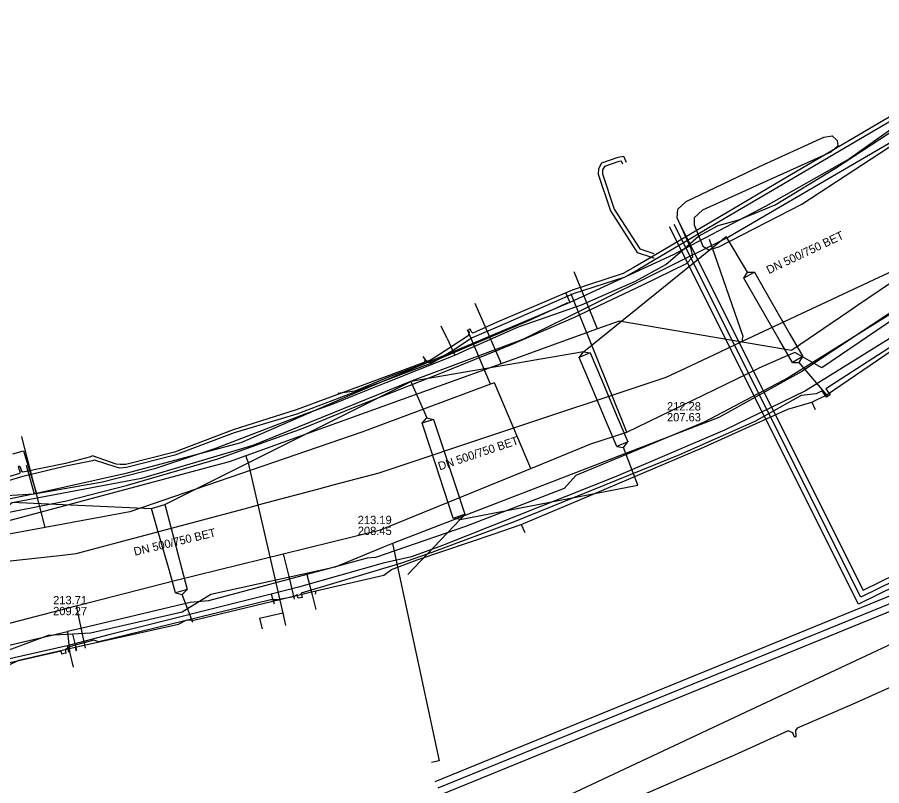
# Model space of a CAD drawing. Extents: x -600309 to -598967, y -1161267 to -1160292.
# Drawn here: x -599618 to -599534.7, y -1161216.6 to -1161142.6 of the extents above; entities that cross this region are included whole.
import ezdxf

# ---------------------------------------------------------------- set-up
doc = ezdxf.new("R2010")
doc.units = 0
for name, color, linetype in [('Vrstva 12', 7, 'Continuous'), ('Vrstva 13', 7, 'Continuous'), ('Vrstva 16', 7, 'Continuous'), ('Vrstva 37', 7, 'Continuous'), ('Vrstva 38', 7, 'Continuous'), ('Vrstva 42', 7, 'Continuous'), ('Vrstva 54', 7, 'Continuous'), ('Vrstva 55', 7, 'Continuous'), ('Vrstva 58', 7, 'Continuous'), ('Vrstva 9', 7, 'Continuous')]:
    doc.layers.add(name, color=color, linetype=linetype)

msp = doc.modelspace()

# ---------------------------------------------------------------- linework, layer by layer
at = {"layer": 'Vrstva 12'}
for p, q in [((-599576.56, -1161173.52), (-599577.125, -1161172.329)), ((-599576.56, -1161173.52), (-599577.125, -1161172.329)), ((-599589.565, -1161198.221), (-599589.204, -1161199.616)), ((-599589.56, -1161198.23), (-599589.204, -1161199.616))]:
    msp.add_line(p, q, dxfattribs=at)
for points in [[(-599521.7, -1161144.87), (-599526.65, -1161148.29), (-599537.79, -1161156.19), (-599545.87, -1161160.77), (-599553.69, -1161164.87)], [(-599560.46, -1161168.89), (-599558.43, -1161168), (-599555.5, -1161166.4), (-599553.67, -1161164.8), (-599552.34, -1161163.64), (-599550.44, -1161162.63), (-599548.47, -1161162.08), (-599544.96, -1161160.64), (-599539.13, -1161157.11), (-599529.68, -1161150.91)], [(-599513.31, -1161157.36), (-599514.8, -1161158.38), (-599542.4, -1161176.7), (-599550.4, -1161181.13), (-599580.66, -1161192.82)], [(-599553.69, -1161164.87), (-599554.78, -1161165.44)], [(-599554.78, -1161165.44), (-599564.73, -1161170.04)], [(-599574.64, -1161174.59), (-599569.69, -1161172.4), (-599563.61, -1161170.27), (-599560.46, -1161168.89)], [(-599565.12, -1161169.15), (-599564.73, -1161170.04)], [(-599564.73, -1161170.04), (-599586.21, -1161179.11), (-599596.44, -1161183.57)], [(-599533.66, -1161171.05), (-599543.7, -1161177.29), (-599551.8, -1161181.57), (-599564.18, -1161186.71), (-599565.3, -1161187.97), (-599574.8, -1161191.62), (-599583.47, -1161194.61), (-599584.26, -1161194.68), (-599587.79, -1161195.63)], [(-599576.56, -1161173.52), (-599575.81, -1161175.11)], [(-599575.81, -1161175.11), (-599574.64, -1161174.59)], [(-599616.34, -1161188.47), (-599609.76, -1161187.32), (-599604.63, -1161186), (-599598.84, -1161184.09), (-599590.23, -1161180.76), (-599587.56, -1161179.8), (-599585.34, -1161178.92), (-599582.44, -1161177.75), (-599575.81, -1161175.11)], [(-599596.44, -1161183.57), (-599607.65, -1161186.57), (-599616.14, -1161188.46)], [(-599618.42, -1161184.62), (-599617.37, -1161184.34), (-599616.14, -1161188.46)], [(-599617.13, -1161185.71), (-599616.34, -1161188.47)], [(-599616.14, -1161188.46), (-599627.44, -1161190.76), (-599644.99, -1161193.72), (-599655.61, -1161195.18), (-599659.69, -1161195.76)], [(-599642.07, -1161193.68), (-599639.42, -1161193.16), (-599622.53, -1161189.29), (-599620.66, -1161188.74), (-599616.34, -1161188.47)], [(-599581.84, -1161193.27), (-599582.62, -1161193.58), (-599587.34, -1161195.54)], [(-599580.66, -1161192.82), (-599581.84, -1161193.27)], [(-599581.84, -1161193.27), (-599577.34, -1161214.2), (-599578.08, -1161214.36)], [(-599587.34, -1161195.54), (-599599.33, -1161198.18), (-599602.08, -1161199.87), (-599610.93, -1161201.9)], [(-599587.79, -1161195.63), (-599590.08, -1161196.25)], [(-599590.08, -1161196.25), (-599599.56, -1161198.8), (-599601.31, -1161198.95), (-599611.18, -1161201.3)], [(-599590.08, -1161196.25), (-599589.56, -1161198.23)], [(-599611.18, -1161201.3), (-599613.15, -1161201.76)], [(-599628.27, -1161205.28), (-599613.15, -1161201.76)], [(-599615.01, -1161202.14), (-599616.64, -1161202.75)], [(-599612.66, -1161202), (-599615.01, -1161202.14)], [(-599613.15, -1161201.76), (-599612.95, -1161203.7)], [(-599610.93, -1161201.9), (-599612.66, -1161202)], [(-599612.66, -1161202), (-599612.28, -1161203.54)], [(-599616.64, -1161202.75), (-599619.06, -1161203.65)], [(-599612.948, -1161203.716), (-599612.602, -1161205.176)], [(-599612.948, -1161203.716), (-599612.602, -1161205.176)]]:
    msp.add_lwpolyline(points, dxfattribs=at)
at = {"layer": 'Vrstva 13'}
for points in [[(-599411.725, -1161101.732), (-599414.519, -1161102.315), (-599450.573, -1161109.837), (-599460.653, -1161116.976), (-599462.737, -1161118.461), (-599483.111, -1161132.905), (-599490.491, -1161138.137), (-599508.933, -1161151.212), (-599509.583, -1161151.672), (-599510.091, -1161152.018), (-599523.741, -1161161.304), (-599533.935, -1161168.24), (-599537.024, -1161170.341), (-599537.86, -1161170.91)], [(-599548.15, -1161173.861), (-599548.1, -1161173.57), (-599548.057, -1161173.319), (-599551.27, -1161163.96)], [(-599562.071, -1161172.593), (-599562.17, -1161172.353), (-599564.326, -1161167.076)], [(-599571.356, -1161175.949), (-599571.43, -1161175.741), (-599571.542, -1161175.432), (-599573.865, -1161170.156)], [(-599537.86, -1161170.91), (-599543.392, -1161174.673), (-599548.15, -1161173.861), (-599559.979, -1161171.842), (-599562.071, -1161172.593), (-599566.524, -1161174.205), (-599571.356, -1161175.949), (-599595.97, -1161184.837), (-599597.571, -1161185.415), (-599619.405, -1161191.232), (-599620.782, -1161191.423), (-599624.139, -1161191.904), (-599629.632, -1161192.702), (-599642.902, -1161194.86), (-599648.23, -1161195.68), (-599648.859, -1161195.765), (-599659.02, -1161197.088), (-599667.384, -1161198.09), (-599681.799, -1161199.818), (-599690.595, -1161200.894), (-599706.57, -1161202.75)], [(-599595.97, -1161184.837), (-599595.861, -1161185.14), (-599595.783, -1161185.354), (-599592.407, -1161199.992), (-599592.153, -1161201.162)], [(-599592.407, -1161199.992), (-599594.634, -1161200.506), (-599594.377, -1161201.491)]]:
    msp.add_lwpolyline(points, dxfattribs=at)
at = {"layer": 'Vrstva 16'}
for points in [[(-599362.74, -1161135.03), (-599363.49, -1161135.7), (-599365.97, -1161134.6), (-599372.85, -1161131.57), (-599390.62, -1161123.28), (-599395.67, -1161110.31), (-599395.85, -1161109.84), (-599431.51, -1161116.63), (-599437.98, -1161113.92), (-599446.12, -1161118), (-599467.25, -1161128.61), (-599480.16, -1161135.09), (-599482.54, -1161136.74), (-599491.58, -1161143), (-599506.15, -1161153.54), (-599506.77, -1161153.95), (-599507.46, -1161154.42), (-599517.51, -1161160.75), (-599532.48, -1161170.92), (-599540.46, -1161176.34), (-599543.07, -1161174.85), (-599544.186, -1161175.34), (-599546.53, -1161176.37)], [(-599564.53, -1161169.47), (-599564.61, -1161169.22)], [(-599559.25, -1161182.53), (-599559.57, -1161181.74), (-599564.53, -1161169.47)], [(-599572.38, -1161177.92), (-599574.6, -1161172.69)], [(-599694.08, -1161216.37), (-599693.354, -1161216.231), (-599678.12, -1161213.31), (-599663.39, -1161210.44), (-599645.7, -1161206.98), (-599632.82, -1161204.18), (-599623.19, -1161202.09), (-599612.32, -1161199.28), (-599602.8, -1161196.83), (-599592.37, -1161194.26), (-599583, -1161191.95), (-599568.5, -1161186.03), (-599562.73, -1161183.67), (-599559.25, -1161182.53), (-599546.53, -1161176.37)], [(-599568.5, -1161186.03), (-599572.01, -1161177.78), (-599572.38, -1161177.92), (-599584.77, -1161182.55), (-599607.13, -1161190.22), (-599615.3, -1161191.73), (-599626.85, -1161193.85), (-599642.17, -1161196.39), (-599649.76, -1161197.64), (-599655.19, -1161198.53), (-599665.78, -1161200.41), (-599689.68, -1161204.63), (-599693.75, -1161205.47)], [(-599615.3, -1161191.73), (-599617.53, -1161182.98), (-599617.53, -1161182.97)], [(-599592.37, -1161194.26), (-599591.795, -1161196.588), (-599591.29, -1161198.63)], [(-599612.32, -1161199.28), (-599611.53, -1161202.92), (-599611.43, -1161203.36)]]:
    msp.add_lwpolyline(points, dxfattribs=at)
at = {"layer": 'Vrstva 37'}
for points in [[(-599519.147, -1161198.094), (-599522.361, -1161191.397), (-599536.715, -1161198.447), (-599554.678, -1161162.517)], [(-599518.301, -1161197.832), (-599519.147, -1161198.094), (-599531.852, -1161202.037), (-599533.206, -1161198.785), (-599577.45, -1161216.847)]]:
    msp.add_lwpolyline(points, dxfattribs=at)
at = {"layer": 'Vrstva 38'}
for points in [[(-599554.23, -1161162.294), (-599536.49, -1161197.779), (-599522.128, -1161190.726), (-599518.97, -1161197.306)], [(-599519.936, -1161197.606), (-599522.593, -1161192.068), (-599536.941, -1161199.114), (-599555.125, -1161162.741)], [(-599577.714, -1161216.199), (-599532.827, -1161197.874), (-599531.451, -1161201.18), (-599519.523, -1161197.478)], [(-599518.987, -1161198.777), (-599532.253, -1161202.895), (-599533.585, -1161199.695), (-599577.185, -1161217.495)]]:
    msp.add_lwpolyline(points, dxfattribs=at)
at = {"layer": 'Vrstva 42'}
for points in [[(-599528.882, -1161148.934), (-599529.827, -1161149.3), (-599533.984, -1161152.191), (-599544.869, -1161158.584), (-599548.329, -1161160.636), (-599556.881, -1161165.68), (-599558.628, -1161166.711)], [(-599528.59, -1161149.15), (-599529.72, -1161149.58), (-599533.768, -1161152.529), (-599544.669, -1161158.93), (-599550.801, -1161162.524), (-599558.119, -1161166.878)], [(-599559.281, -1161156.565), (-599559.531, -1161155.974), (-599560.12, -1161156.086), (-599561.692, -1161156.621), (-599561.983, -1161157.161), (-599562.003, -1161157.692), (-599560.827, -1161161.218), (-599558.265, -1161165.225), (-599556.881, -1161165.68), (-599556.615, -1161165.768)], [(-599559.649, -1161156.721), (-599559.773, -1161156.428), (-599560.018, -1161156.474), (-599561.414, -1161156.949), (-599561.587, -1161157.269), (-599561.601, -1161157.634), (-599560.463, -1161161.044), (-599558.005, -1161164.889), (-599556.659, -1161165.332)], [(-599558.628, -1161166.711), (-599559.595, -1161167.263), (-599564.51, -1161168.87), (-599571.73, -1161171.95), (-599574.076, -1161172.987), (-599574.254, -1161172.851), (-599574.32, -1161172.661), (-599574.44, -1161172.62), (-599574.506, -1161172.735), (-599574.438, -1161172.931), (-599574.539, -1161173.264), (-599576.32, -1161174.41), (-599578.09, -1161175.58), (-599584.48, -1161177.96), (-599591.11, -1161180.4), (-599597.18, -1161182.33), (-599602.82, -1161184.46), (-599607.52, -1161185.66), (-599608.06, -1161185.67), (-599608.46, -1161185.64), (-599610.74, -1161184.81), (-599610.93, -1161184.92), (-599613.34, -1161185.55), (-599617.45, -1161186.39), (-599617.509, -1161186.351), (-599617.688, -1161185.866), (-599617.819, -1161185.801), (-599617.885, -1161185.908), (-599617.706, -1161186.392), (-599617.77, -1161186.52), (-599624.34, -1161188.52)], [(-599558.119, -1161166.878), (-599559.459, -1161167.605), (-599564.42, -1161169.2), (-599571.53, -1161172.33), (-599574.14, -1161173.45), (-599576.04, -1161174.69), (-599577.99, -1161175.87), (-599584.31, -1161178.23), (-599591.05, -1161180.8), (-599597.09, -1161182.61), (-599602.79, -1161184.77), (-599607.45, -1161185.94), (-599608.11, -1161186.01), (-599608.55, -1161185.89), (-599610.53, -1161185.25), (-599610.75, -1161185.29), (-599613.3, -1161185.83), (-599617.46, -1161186.82), (-599624.24, -1161188.82)], [(-599532.02, -1161173.15), (-599540.074, -1161178.371), (-599539.674, -1161178.952), (-599539.839, -1161179.065), (-599540.004, -1161179.179), (-599540.427, -1161178.565), (-599541.01, -1161178.86), (-599542.45, -1161179), (-599546.93, -1161181.5), (-599554.16, -1161184.72), (-599570.12, -1161191.19), (-599578.03, -1161194.15), (-599580.96, -1161195.16), (-599590.636, -1161198.053), (-599590.541, -1161198.458), (-599590.736, -1161198.504), (-599590.931, -1161198.55), (-599591.012, -1161198.207), (-599591.35, -1161198.4), (-599592.95, -1161198.69), (-599593.55, -1161198.69), (-599610.13, -1161202.73), (-599610.59, -1161202.57), (-599612.85, -1161203.19), (-599613.376, -1161203.481), (-599613.297, -1161203.828), (-599613.492, -1161203.872), (-599613.687, -1161203.917), (-599613.751, -1161203.637), (-599628.45, -1161207)], [(-599532.459, -1161206.49), (-599537.549, -1161208.77), (-599542.84, -1161211.05), (-599543, -1161211.29), (-599542.968, -1161211.82), (-599543.024, -1161211.922), (-599543.131, -1161211.871), (-599543.27, -1161211.5), (-599543.69, -1161211.32), (-599548.869, -1161213.67), (-599557.22, -1161217.29), (-599562.489, -1161219.54), (-599562.809, -1161219.95), (-599562.761, -1161220.281), (-599562.845, -1161220.476), (-599562.998, -1161220.39)]]:
    msp.add_lwpolyline(points, dxfattribs=at)
at = {"layer": 'Vrstva 54'}
for points in [[(-599563.43, -1161174.81), (-599549.67, -1161163.69)], [(-599547.63, -1161167.13), (-599549.67, -1161163.69)], [(-599546.963, -1161167.13), (-599547.966, -1161167.706), (-599547.63, -1161167.13), (-599546.963, -1161167.13)], [(-599546.963, -1161167.13), (-599545.43, -1161169.8)], [(-599546.46, -1161170.33), (-599547.966, -1161167.706)], [(-599545.43, -1161169.8), (-599543.54, -1161173.09)], [(-599544.54, -1161173.68), (-599546.46, -1161170.33)], [(-599543.54, -1161173.09), (-599542.294, -1161175.264)], [(-599543.297, -1161175.84), (-599544.54, -1161173.68)], [(-599563.43, -1161174.81), (-599580.05, -1161177.66)], [(-599562.768, -1161174.892), (-599563.834, -1161175.34), (-599563.43, -1161174.81), (-599562.768, -1161174.892)], [(-599562.768, -1161174.892), (-599561.6, -1161177.68)], [(-599562.65, -1161178.15), (-599563.834, -1161175.34)], [(-599542.294, -1161175.264), (-599543.297, -1161175.84), (-599542.63, -1161175.84), (-599542.294, -1161175.264)], [(-599539.85, -1161179.09), (-599542.63, -1161175.84)], [(-599603.77, -1161189.52), (-599580.05, -1161177.66)], [(-599580.05, -1161177.66), (-599578.53, -1161181.17)], [(-599561.14, -1161181.75), (-599562.65, -1161178.15)], [(-599561.6, -1161177.68), (-599560.11, -1161181.22)], [(-599577.877, -1161181.305), (-599578.976, -1161181.666), (-599578.53, -1161181.17), (-599577.877, -1161181.305)], [(-599577.877, -1161181.305), (-599577.08, -1161183.74)], [(-599560.11, -1161181.22), (-599559.156, -1161183.48)], [(-599578.18, -1161184.11), (-599578.976, -1161181.666)], [(-599560.222, -1161183.928), (-599561.14, -1161181.75)], [(-599576.85, -1161188.15), (-599578.18, -1161184.11)], [(-599577.08, -1161183.74), (-599575.74, -1161187.82)], [(-599559.156, -1161183.48), (-599560.222, -1161183.928), (-599559.56, -1161184.01), (-599559.156, -1161183.48)], [(-599558.19, -1161187.65), (-599559.56, -1161184.01)], [(-599575.973, -1161190.815), (-599576.85, -1161188.15)], [(-599575.74, -1161187.82), (-599574.874, -1161190.454)], [(-599575.32, -1161190.95), (-599558.19, -1161187.65)], [(-599618.51, -1161189.27), (-599605.05, -1161189.89)], [(-599605.05, -1161189.89), (-599603.77, -1161189.52)], [(-599604.5, -1161191.82), (-599605.05, -1161189.89)], [(-599603.77, -1161189.52), (-599603.23, -1161191.56)], [(-599574.874, -1161190.454), (-599575.32, -1161190.95), (-599575.973, -1161190.815), (-599574.874, -1161190.454)], [(-599603.23, -1161191.56), (-599602.17, -1161195.6)], [(-599580.36, -1161196.24), (-599575.32, -1161190.95)], [(-599603.33, -1161195.9), (-599604.5, -1161191.82)], [(-599602.17, -1161195.6), (-599601.611, -1161197.707)], [(-599602.725, -1161198.013), (-599603.33, -1161195.9)], [(-599601.611, -1161197.707), (-599602.725, -1161198.013), (-599602.08, -1161198.18), (-599601.611, -1161197.707)], [(-599601.07, -1161200.89), (-599602.08, -1161198.18)]]:
    msp.add_lwpolyline(points, dxfattribs=at)
at = {"layer": 'Vrstva 55'}
for points in [[(-599532.87, -1161154.08), (-599549.46, -1161163.75), (-599569.2, -1161173.57), (-599579.92, -1161177.58), (-599595.28, -1161183.83), (-599606, -1161187.01), (-599618.49, -1161189.35), (-599619.64, -1161190.24), (-599637.31, -1161193.76), (-599653.77, -1161196.3), (-599692.79, -1161202.08)], [(-599572.08, -1161226.46), (-599572.79, -1161226.01), (-599573.1, -1161226.15), (-599574.59, -1161221.93), (-599566.29, -1161218.18), (-599547.28, -1161209.27), (-599529.58, -1161200.97), (-599521.55, -1161197.1), (-599519.16, -1161197.74), (-599518.34, -1161199.25), (-599516.89, -1161202.34), (-599517.98, -1161202.95)]]:
    msp.add_lwpolyline(points, dxfattribs=at)
at = {"layer": 'Vrstva 58'}
for p, q in [((-599578.71, -1161175.47), (-599578.86, -1161175.25)), ((-599541.43, -1161179.66), (-599541.11, -1161180.36)), ((-599569.43, -1161191.43), (-599569.07, -1161192.2)), ((-599589.2, -1161197.82), (-599589.29, -1161198.16)), ((-599612.4, -1161203.26), (-599612.31, -1161203.6))]:
    msp.add_line(p, q, dxfattribs=at)
for points in [[(-599623.52, -1161191.18), (-599613.24, -1161189.16), (-599607.35, -1161187.64), (-599598.65, -1161185.1), (-599590.43, -1161182.15), (-599585.74, -1161180.24), (-599577.34, -1161176.92), (-599570.36, -1161174.09), (-599564.36, -1161171.48), (-599557.71, -1161168.34), (-599553.5, -1161166.29), (-599552.9, -1161165.63), (-599553.04, -1161164.87), (-599554.4, -1161161.9), (-599554.33, -1161161.04), (-599553.54, -1161160.31), (-599546.46, -1161156.95), (-599540.27, -1161154.1), (-599539.46, -1161154), (-599538.98, -1161154.44), (-599538.93, -1161154.95), (-599539.58, -1161155.57), (-599545.79, -1161158.36), (-599551.96, -1161161.14), (-599552.77, -1161161.88), (-599552.75, -1161162.57), (-599551.94, -1161164.62), (-599551.34, -1161164.97), (-599550.4, -1161164.67), (-599542.38, -1161160.56), (-599533.2, -1161154.58)], [(-599541.43, -1161179.66), (-599540.06, -1161178.99), (-599521.86, -1161166.57)], [(-599564.98, -1161170.09), (-599565.64, -1161170.41), (-599568.73, -1161171.8), (-599578.21, -1161175.86), (-599578.46, -1161175.8), (-599578.71, -1161175.47)], [(-599531.86, -1161172.24), (-599542.03, -1161178.55), (-599549.85, -1161182.35), (-599560.267, -1161186.822), (-599576.998, -1161193.457), (-599580.01, -1161194.54), (-599582.739, -1161195.164), (-599590.88, -1161197.47), (-599591.88, -1161197.74), (-599593.51, -1161198.15)], [(-599578.71, -1161175.47), (-599578.76, -1161175.89), (-599579.06, -1161176.05), (-599582.21, -1161177.23), (-599585.46, -1161178.6), (-599587.1, -1161178.8)], [(-599569.43, -1161191.43), (-599562.5, -1161188.51), (-599551.82, -1161183.98), (-599543.73, -1161180.32), (-599541.43, -1161179.66)], [(-599589.2, -1161197.82), (-599582.65, -1161196.31), (-599581.93, -1161195.79), (-599579.44, -1161194.84), (-599572.03, -1161192.35), (-599569.43, -1161191.43)], [(-599593.51, -1161198.15), (-599609.029, -1161202.043), (-599613.19, -1161203.13)], [(-599612.4, -1161203.26), (-599602.46, -1161201.03), (-599601.66, -1161200.62), (-599600.97, -1161200.67), (-599589.2, -1161197.82)], [(-599593.51, -1161198.15), (-599593.24, -1161199.07)], [(-599625.75, -1161206.51), (-599624.39, -1161206.37), (-599618.89, -1161205.01), (-599617.83, -1161204.5), (-599612.4, -1161203.26)], [(-599613.19, -1161203.13), (-599615.17, -1161203.59), (-599618.98, -1161204.46)], [(-599613.19, -1161203.13), (-599613.05, -1161203.74)]]:
    msp.add_lwpolyline(points, dxfattribs=at)
at = {"layer": 'Vrstva 9'}
for points in [[(-599555.45, -1161177.23), (-599553.591, -1161176.358), (-599550.789, -1161175.044), (-599547.556, -1161173.528), (-599535.405, -1161167.829), (-599531.894, -1161166.182), (-599524.79, -1161162.85)], [(-599583.116, -1161186.447), (-599571.095, -1161182.442), (-599564.852, -1161180.362), (-599562.689, -1161179.642), (-599555.45, -1161177.23)], [(-599612.3, -1161194.24), (-599595.643, -1161189.792), (-599594.406, -1161189.462), (-599588.914, -1161187.995), (-599587.41, -1161187.594), (-599583.116, -1161186.447)], [(-599632.02, -1161196.42), (-599631.324, -1161196.343), (-599619.546, -1161195.041), (-599613.612, -1161194.385), (-599612.3, -1161194.24)]]:
    msp.add_lwpolyline(points, dxfattribs=at)

# ---------------------------------------------------------------- texts
at = {"layer": 'Vrstva 12'}
for rotation, p in [(25.43933, (-599545.569, -1161167.326)), (18.44924, (-599577.282, -1161186.231)), (13.5218, (-599606.657, -1161194.457))]:
    msp.add_text('DN 500/750 BET', height=0.8, rotation=rotation, dxfattribs=at).set_placement(p)
for s, p in [('212.28', (-599555.385, -1161180.449)), ('207.63', (-599555.385, -1161181.499)), ('213.19', (-599585.175, -1161191.4)), ('208.45', (-599585.175, -1161192.45)), ('213.71', (-599614.527, -1161199.127)), ('209.27', (-599614.527, -1161200.177))]:
    msp.add_text(s, height=0.8, dxfattribs=at).set_placement(p)

doc.saveas('drawing.dxf')
